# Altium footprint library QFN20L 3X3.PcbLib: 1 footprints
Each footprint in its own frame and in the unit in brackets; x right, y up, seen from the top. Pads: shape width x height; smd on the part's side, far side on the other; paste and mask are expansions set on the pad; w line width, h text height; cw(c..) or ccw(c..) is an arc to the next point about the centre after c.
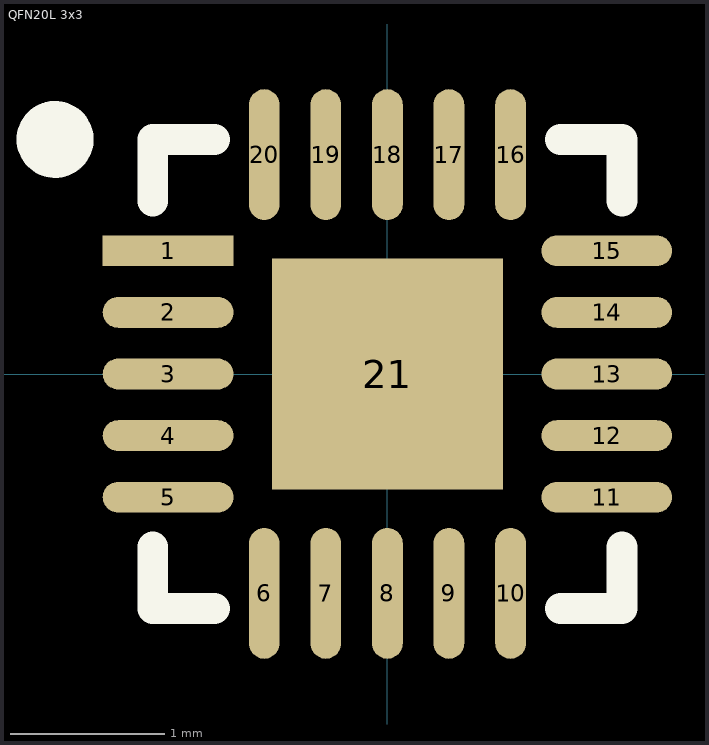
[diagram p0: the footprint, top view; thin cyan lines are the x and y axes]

## QFN20L 3x3 [mm] "QFN, 20-Leads, Body 3.00x3.00mm, Pitch 0.40mm, Thermal Pad 1.60x1.60mm, IPC Medium Density"
height 0.8
pads (21):
  rect 0.85x0.2 smd: 1(-1.425,0.8)
  oval 0.85x0.2 smd: 2(-1.425,0.4) 3(-1.425,0) 4(-1.425,-0.4) 5(-1.425,-0.8) 11(1.425,-0.8) 12(1.425,-0.4) 13(1.425,0) 14(1.425,0.4) 15(1.425,0.8)
  oval 0.2x0.85 smd: 6(-0.8,-1.425) 7(-0.4,-1.425) 8(0,-1.425) 9(0.4,-1.425) 10(0.8,-1.425) 16(0.8,1.425) 17(0.4,1.425) 18(0,1.425) 19(-0.4,1.425) 20(-0.8,1.425)
  rect 1.5x1.5 smd: 21(0,0)
Top Overlay:
  circle w0.25: c-2.159,1.524 r0.125
  lines w0.2: -1.524,-1.124 -1.524,-1.524 -1.124,-1.524 ; -1.524,1.124 -1.524,1.524 -1.124,1.524 ; 1.124,-1.524 1.524,-1.524 1.524,-1.124 ; 1.124,1.524 1.524,1.524 1.524,1.124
